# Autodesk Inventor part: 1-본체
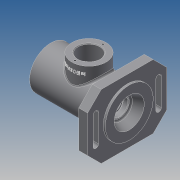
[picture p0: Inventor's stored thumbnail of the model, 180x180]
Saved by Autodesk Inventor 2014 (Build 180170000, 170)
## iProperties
Created: 2017-10
Part Number: 1-본체
Material: Generic
Document SubType Name: Modeling
Designer: kb543-11
Density: 1 g/cm^3
Appearance: Default
Author: kb543-11
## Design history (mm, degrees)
sketch "스케치1"
  geometry: L1 (-48.5, 0)-(-48.5, 24); L2 (-48.5, 24)-(-45.5, 24); L3 (-45.5, 24)-(-45.5, 20); L4 (-45.5, 20)-(-36.5, 20); L5 (-36.5, 20)-(-36.5, 17.5); L6 (-36.5, 17.5)-(-33.25, 17.5); L7 (-33.25, 17.5)-(-33.25, 18.5); L8 (-33.25, 18.5)-(-31.5, 18.5); L9 (-31.5, 18.5)-(-31.5, 17.5); L10 (-31.5, 17.5)-(-20.5, 17.5); L11 (-20.5, 17.5)-(-20.5, 26); L12 (-20.5, 26)-(17.5, 26); L13 (17.5, 26)-(17.5, 17.5); L14 (33.3, 16.5)-(33.3, 10); L15 (33.3, 10)-(36, 10); L16 (36, 10)-(36, 12.5); L17 (36, 12.5)-(42.8, 12.5); L18 (43.5, 16)-(57.5, 22); L19 (57.5, 22)-(57.5, 35); L20 (57.5, 0)-(-57.5, 0); L21 (43.5, 16)-(43.5, 12.904); L22 (42.8, 12.5)-(43.5, 12.904); L23 (17.5, 17.5)-(28.5, 17.5); L24 (28.5, 17.5)-(28.5, 16.5); L25 (28.5, 16.5)-(33.3, 16.5); L26 (-57.5, 31)-(-57.5, 0); L27 (57.5, 35)-(54.5, 35); L28 (-57.5, 31)-(54.5, 31); L29 (54.5, 31)-(54.5, 35); 2 further points
  constraints: 58 end point, 11 parallel, 5 perpendicular, 1 coincident, 1 midpoint, 1 point on line, 1 vertical, 1 vertical alignment
  dimensions: "d1" = 48 diameter of L2 L20; "d4" = 3 distance of L1.end L2.end; "d7" = 40 diameter of L4 L20; "d8" = 35 diameter of L6 L20; "d9" = 1.75 distance of L7.end L8.end; "d10" = 37 diameter of L8 L20; "d12" = 11 distance of L9.end L10.end; "d13" = 35 diameter of L10 L20; "d14" = 52 diameter of L12 L20; "d15" = 32 diameter of L18.start L20; "d16" = 44 diameter of L18.end L20; "d18" = 38 distance between parallel lines of L13 L11; "d19" = 14 distance between parallel lines of L19 L21; "d24" = 30 deg angle of L22 L17; "d25" = 0.7 horizontal distance of L21.end L17.end; "d26" = 7.5 distance between parallel lines of L16 L21; "d28" = 25 diameter of L17 L20; "d29" = 2.7 distance of L14.end L15.end; "d30" = 20 diameter of L15 L20; "d31" = 35 diameter of L23 L20; "d32" = 33 diameter of L25 L20; "d33" = 11 distance between parallel lines of L24 L13; "d90" = 12 distance between parallel lines of L3 L26; "d91" = 115 distance between parallel lines of L19 L26; "d92" = 21 distance between parallel lines of L26 L5; "d93" = 26 distance between parallel lines of L26 L9; "d101" = 62 diameter of L28 L20; "d102" = 3 distance of L19.end L27.end; "d103" = 70 diameter of L27 L20
revolve "회전1" sketch "스케치1" stored, may be unused: angle "d34" = 90 deg
sketch "스케치8"
  geometry: C1 r 31 at (0, 0) reference; 1 further point
  constraints: 1 coincident
hole "구멍2" sketch "스케치8" at (0, 0) diameter "d94" = 40.376; stored, may be unused: countersink angle "d98" = 90 deg, drill point angle "d100" = 118 deg; dims "d95" = 6, "d96" = 4, "d97" = 2, "d99" = 8
node "작업 평면1"
sketch "스케치2"
  geometry: L1 (-38, 47)-(38, 47); L2 (58, 27)-(58, -27); L3 (38, -47)-(-38, -47); L4 (-58, -27)-(-58, 27); L5 (-58, 47)-(58, -47); L6 (58, 47)-(-58, -47); L7 (-38, 47)-(-58, 27); L8 (-58, -27)-(-38, -47); L9 (38, -47)-(58, -27); L10 (58, 27)-(38, 47); C1 r 31 at (0, 0) reference; 1 further point
  constraints: 20 end point, 8 point on line, 2 midpoint, 2 parallel, 1 horizontal, 1 perpendicular
  dimensions: "d39" = 116 distance of L5.start L6.start; "d40" = 94 distance of L6.start L5.end; "d41" = 20 distance of L1.start L5.start; "d42" = 20 distance of L4.end L5.start (= d41); "d43" = 20 distance of L4.start L6.end (= d41); "d44" = 20 distance of L3.end L6.end (= d43); "d45" = 20 distance of L3.start L5.end (= d41); "d46" = 20 distance of L2.end L5.end (= d45); "d47" = 20 distance of L2.start L6.start; "d48" = 20 distance of L1.end L6.start (= d47)
extrude "돌출5" join sketch "스케치2" distance "d104" = 13; taper "d105" = 0 deg
sketch "스케치9"
  geometry: L1 (58, -27)-(58, 27) reference; L2 (46, -20)-(46, 20); L3 (42, -20)-(42, 20); L4 (50, 20)-(50, -20); L5 (-46, -20)-(-46, 20); L6 (-50, -20)-(-50, 20); L7 (-42, 20)-(-42, -20); C1 r 31 at (0, 0) reference; A1 r 4 centre (46, -20) between (42, -20) and (50, -20); A2 r 4 centre (46, 20) between (50, 20) and (42, 20); A3 r 4 centre (-46, -20) between (-50, -20) and (-42, -20); A4 r 4 centre (-46, 20) between (-42, 20) and (-50, 20); 2 further points
  constraints: 16 end point, 8 point on circle, 8 tangent, 4 centre point, 4 parallel, 3 horizontal alignment, 2 midpoint
  dimensions: "d106" = 46 distance from line of L2 C1.centre; "d107" = 92 distance between parallel lines of L5 L2; "d108" = 4 radius of A3; "d109" = 4 radius of A1; "d110" = 40 distance of L5.start L5.end
extrude "돌출6" cut sketch "스케치9" stored distance "d111" = 13; taper "d112" = 0 deg
node "작업 평면2"
sketch "스케치4"
  geometry: L1 (57.5, 31)-(57.5, -31) reference; C1 r 25 at (1.5, 0); 2 further points
  constraints: 1 centre point, 1 horizontal alignment, 1 midpoint
  dimensions: "d58" = 50 diameter of C1; "d59" = 56 distance from line of L1 C1.centre
extrude "돌출3" join sketch "스케치4" stored distance "d60" = 13; taper "d61" = 0 deg
sketch "스케치5"
  geometry: C1 r 25 at (0, 0) reference; C2 r 16 at (0, 0); 1 further point
  constraints: 1 centre point, 1 coincident
  dimensions: "d62" = 32 diameter of C2
extrude "돌출4" cut sketch "스케치5" stored distance "d63" = 13; taper "d64" = 0 deg
node "작업 평면3"
sketch "스케치6"
  geometry: L1 (-56, -78)-(-56, -16) reference; L2 (-25, 0)-(25, 0) reference; 2 further points
  constraints: 1 other
  dimensions: "d65" = 56 distance from line of L1 point (0, -10); "d66" = 10 distance from line of point (0, -10) L2
feature "엠보싱1" sketch "스케치6" dims "d1" = 48, "d4" = 3, "d7" = 40, "d8" = 35, "d9" = 1.75, "d10" = 37, "d12" = 11, "d13" = 35, "d14" = 52, "d15" = 32, "d16" = 44, "d18" = 38, "d19" = 14, "d24" = 30 deg, "d25" = 0.7, "d26" = 7.5, "d28" = 25, "d29" = 2.7, "d30" = 20, "d31" = 35, "d32" = 33, "d33" = 11, "d67" = 0.5, "d68" = 0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
sketch "스케치7"
  geometry: C1 r 16 at (0, 0) reference; 3 further points
  constraints: 2 vertical alignment
  dimensions: "d69" = 20.5 distance of C1.centre point (0, 20.5); "d70" = 41 distance of point (0, -20.5) point (0, 20.5)
hole "구멍1" sketch "스케치7" at (0, 20.5), (0, -20.5) diameter "d71" = 2.459; stored, may be unused: countersink angle "d75" = 90 deg, drill point angle "d77" = 118 deg; dims "d72" = 6, "d73" = 4, "d74" = 2, "d76" = 8
fillet "모깎기2" dims "d79" = 3
fillet "모깎기3" dims "d80" = 0.3
fillet "모깎기4" dims "d81" = 0.3
fillet "모깎기5" dims "d82" = 3
chamfer "모따기1" distance "d84" = 1; stored, may be unused: second distance "d85" = 2, angle "d86" = 45 deg
chamfer "모따기2" distance "d87" = 1; stored, may be unused: second distance "d88" = 2, angle "d89" = 45 deg
fillet "모깎기7" dims "d113" = 3
node "솔리드1"
other parameters: "d38" = -3, "d57" = 47
